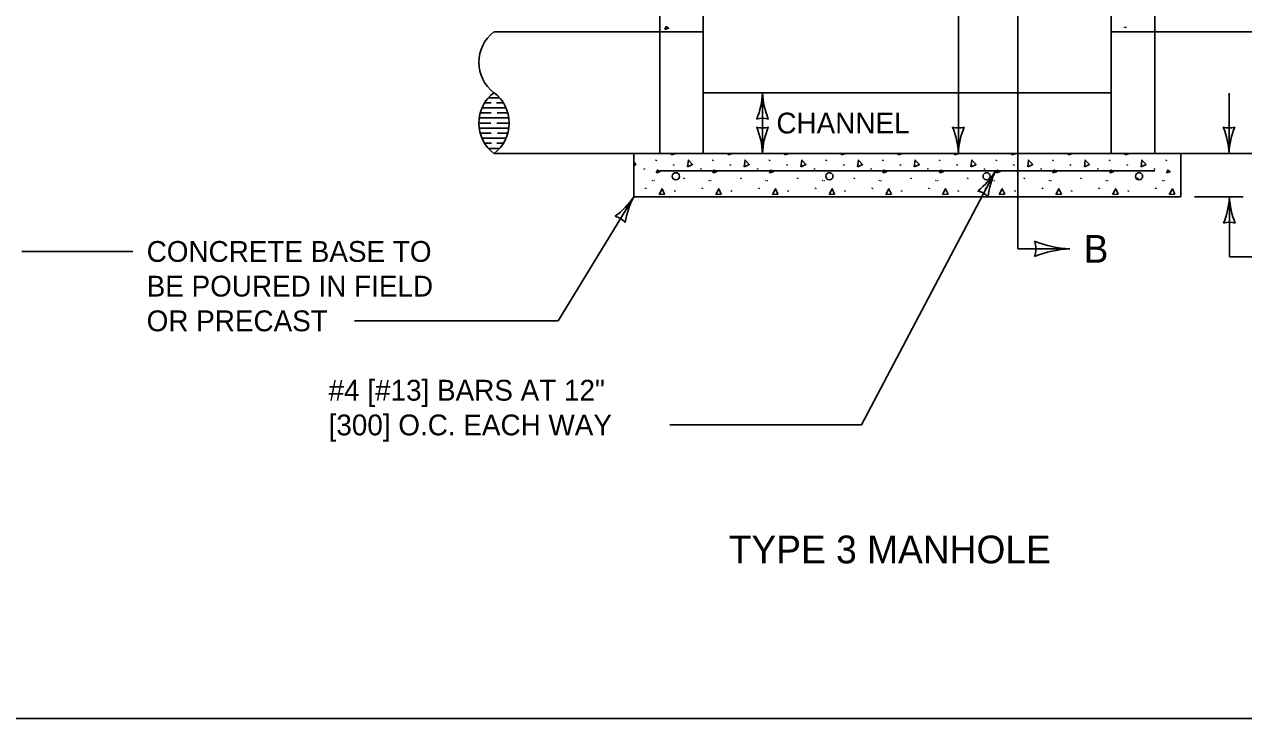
# Model space of a CAD drawing. Extents: x 49991.4 to 50028.3, y 49987.6 to 50011.4.
# Drawn here: x 50005.208 to 50008.719, y 49987.799 to 49989.8 of the extents above; entities that cross this region are included whole.
import ezdxf

# ---------------------------------------------------------------- set-up
doc = ezdxf.new("R2010")
doc.units = 0
for name, color, linetype in [('Level 1', 7, 'Continuous'), ('Level 2', 7, 'Continuous'), ('Level 3', 7, 'Continuous'), ('Level 4', 7, 'Continuous'), ('Level 6', 7, 'Continuous')]:
    doc.layers.add(name, color=color, linetype=linetype)

msp = doc.modelspace()

# ---------------------------------------------------------------- linework, layer by layer
at = {"layer": 'Level 1'}
for p, q in [((50007.0376, 49991.4777), (50007.0376, 49989.7777)), ((50008.4626, 49991.4777), (50008.4626, 49989.7777)), ((50007.1626, 49989.7777), (50006.5599, 49989.7777)), ((50008.3376, 49989.7777), (50008.9435, 49989.7777)), ((50008.3737, 49989.7929), (50008.3751, 49989.7909)), ((50008.3788, 49989.7921), (50008.3801, 49989.7901)), ((50007.1626, 49989.6027), (50008.3376, 49989.6027)), ((50006.533, 49989.5736), (50006.5513, 49989.5736)), ((50006.544, 49989.5882), (50006.5758, 49989.5882)), ((50006.567, 49989.5736), (50006.5868, 49989.5736)), ((50006.5201, 49989.5444), (50006.552, 49989.5444)), ((50006.5253, 49989.559), (50006.5945, 49989.559)), ((50006.5693, 49989.5444), (50006.5997, 49989.5444)), ((50006.5161, 49989.5152), (50006.5505, 49989.5152)), ((50006.5171, 49989.5298), (50006.6027, 49989.5298)), ((50006.5171, 49989.5007), (50006.6027, 49989.5007)), ((50006.5677, 49989.5152), (50006.6036, 49989.5152)), ((50006.5201, 49989.4861), (50006.5513, 49989.4861)), ((50006.5253, 49989.4715), (50006.5945, 49989.4715)), ((50006.57, 49989.4861), (50006.5997, 49989.4861)), ((50006.533, 49989.4569), (50006.5527, 49989.4569)), ((50006.544, 49989.4423), (50006.5758, 49989.4423)), ((50007.1626, 49989.4277), (50006.5599, 49989.4277)), ((50006.5684, 49989.4569), (50006.5868, 49989.4569)), ((50006.9626, 49989.4277), (50006.9626, 49989.3027)), ((50008.3376, 49989.4277), (50008.9435, 49989.4277)), ((50008.5376, 49989.4277), (50008.5376, 49989.3027)), ((50007.0261, 49989.4064), (50007.0274, 49989.4094)), ((50007.0767, 49989.3928), (50007.078, 49989.3958)), ((50007.1893, 49989.4064), (50007.1907, 49989.4094)), ((50007.2399, 49989.3928), (50007.2413, 49989.3958)), ((50007.3526, 49989.4064), (50007.3539, 49989.4094)), ((50007.4032, 49989.3928), (50007.4045, 49989.3958)), ((50007.5159, 49989.4064), (50007.5172, 49989.4094)), ((50007.5665, 49989.3928), (50007.5678, 49989.3958)), ((50007.6791, 49989.4064), (50007.6805, 49989.4094)), ((50007.7297, 49989.3928), (50007.7311, 49989.3958)), ((50007.8424, 49989.4064), (50007.8437, 49989.4094)), ((50007.893, 49989.3928), (50007.8943, 49989.3958)), ((50008.0057, 49989.4064), (50008.007, 49989.4094)), ((50008.0563, 49989.3928), (50008.0576, 49989.3958)), ((50008.1689, 49989.4064), (50008.1703, 49989.4094)), ((50008.2195, 49989.3928), (50008.2209, 49989.3958)), ((50008.3322, 49989.4064), (50008.3335, 49989.4094)), ((50008.3828, 49989.3928), (50008.3841, 49989.3958)), ((50008.4955, 49989.4064), (50008.4968, 49989.4094)), ((50006.9926, 49989.3844), (50006.9929, 49989.3814)), ((50007.0376, 49989.3777), (50008.4626, 49989.3777)), ((50007.107, 49989.3541), (50007.1083, 49989.3571)), ((50007.1559, 49989.3844), (50007.1562, 49989.3814)), ((50007.2703, 49989.3541), (50007.2716, 49989.3571)), ((50007.3191, 49989.3844), (50007.3195, 49989.3814)), ((50007.4335, 49989.3541), (50007.4349, 49989.3571)), ((50007.4824, 49989.3844), (50007.4827, 49989.3814)), ((50007.5968, 49989.3541), (50007.5981, 49989.3571)), ((50007.6457, 49989.3844), (50007.646, 49989.3814)), ((50007.7601, 49989.3541), (50007.7614, 49989.3571)), ((50007.8089, 49989.3844), (50007.8093, 49989.3814)), ((50007.9233, 49989.3541), (50007.9247, 49989.3571)), ((50007.9722, 49989.3844), (50007.9725, 49989.3814)), ((50008.0866, 49989.3541), (50008.0879, 49989.3571)), ((50008.1355, 49989.3844), (50008.1358, 49989.3814)), ((50008.2499, 49989.3541), (50008.2512, 49989.3571)), ((50008.2987, 49989.3844), (50008.2991, 49989.3814)), ((50008.4131, 49989.3541), (50008.4145, 49989.3571)), ((50008.462, 49989.3844), (50008.4623, 49989.3814)), ((50006.9957, 49989.3256), (50006.997, 49989.3285)), ((50007.0153, 49989.3503), (50007.0167, 49989.3483)), ((50007.0204, 49989.3495), (50007.0217, 49989.3475)), ((50007.08, 49989.3179), (50007.0813, 49989.3209)), ((50007.1589, 49989.3256), (50007.1603, 49989.3285)), ((50007.1786, 49989.3503), (50007.1799, 49989.3483)), ((50007.1837, 49989.3495), (50007.185, 49989.3475)), ((50007.2433, 49989.3179), (50007.2446, 49989.3209)), ((50007.3222, 49989.3256), (50007.3235, 49989.3285)), ((50007.3419, 49989.3503), (50007.3432, 49989.3483)), ((50007.3469, 49989.3495), (50007.3483, 49989.3475)), ((50007.4065, 49989.3179), (50007.4079, 49989.3209)), ((50007.4855, 49989.3256), (50007.4868, 49989.3285)), ((50007.5051, 49989.3503), (50007.5065, 49989.3483)), ((50007.5102, 49989.3495), (50007.5115, 49989.3475)), ((50007.5698, 49989.3179), (50007.5711, 49989.3209)), ((50007.6487, 49989.3256), (50007.6501, 49989.3285)), ((50007.6684, 49989.3503), (50007.6697, 49989.3483)), ((50007.6735, 49989.3495), (50007.6748, 49989.3475)), ((50007.7331, 49989.3179), (50007.7344, 49989.3209)), ((50007.812, 49989.3256), (50007.8133, 49989.3285)), ((50007.8317, 49989.3503), (50007.833, 49989.3483)), ((50007.8367, 49989.3495), (50007.8381, 49989.3475)), ((50007.8963, 49989.3179), (50007.8977, 49989.3209)), ((50007.9753, 49989.3256), (50007.9766, 49989.3285)), ((50007.9949, 49989.3503), (50007.9963, 49989.3483)), ((50008, 49989.3495), (50008.0013, 49989.3475)), ((50008.0596, 49989.3179), (50008.0609, 49989.3209)), ((50008.1385, 49989.3256), (50008.1399, 49989.3285)), ((50008.1582, 49989.3503), (50008.1595, 49989.3483)), ((50008.1633, 49989.3495), (50008.1646, 49989.3475)), ((50008.2229, 49989.3179), (50008.2242, 49989.3209)), ((50008.3018, 49989.3256), (50008.3031, 49989.3285)), ((50008.3215, 49989.3503), (50008.3228, 49989.3483)), ((50008.3265, 49989.3495), (50008.3279, 49989.3475)), ((50008.3861, 49989.3179), (50008.3875, 49989.3209)), ((50008.4651, 49989.3256), (50008.4664, 49989.3285)), ((50008.4847, 49989.3503), (50008.4861, 49989.3483)), ((50008.4898, 49989.3495), (50008.4911, 49989.3475)), ((50006.9626, 49989.3027), (50008.5376, 49989.3027))]:
    msp.add_line(p, q, dxfattribs=at)
for points in [[(49999.3835, 49998.9992), (50016.7501, 49998.9992), (50016.7501, 49987.7988), (49999.3835, 49987.7988)], [(50007.1626, 49991.4777), (50008.3376, 49991.4777), (50008.3376, 49989.4277), (50007.1626, 49989.4277)]]:
    msp.add_lwpolyline(points, close=True, dxfattribs=at)
for points in [[(50007.0521, 49989.7849), (50007.0561, 49989.7933), (50007.0627, 49989.7883), (50007.0521, 49989.7849)], [(50007.0701, 49989.4236), (50007.072, 49989.4277)], [(50007.0798, 49989.4277), (50007.0807, 49989.4269), (50007.0701, 49989.4236)], [(50007.2333, 49989.4236), (50007.2353, 49989.4277)], [(50007.243, 49989.4277), (50007.244, 49989.4269), (50007.2333, 49989.4236)], [(50007.3966, 49989.4236), (50007.3986, 49989.4277)], [(50007.4063, 49989.4277), (50007.4073, 49989.4269), (50007.3966, 49989.4236)], [(50007.5599, 49989.4236), (50007.5618, 49989.4277)], [(50007.5696, 49989.4277), (50007.5705, 49989.4269), (50007.5599, 49989.4236)], [(50007.7231, 49989.4236), (50007.7251, 49989.4277)], [(50007.7328, 49989.4277), (50007.7338, 49989.4269), (50007.7231, 49989.4236)], [(50007.8864, 49989.4236), (50007.8884, 49989.4277)], [(50007.8961, 49989.4277), (50007.8971, 49989.4269), (50007.8864, 49989.4236)], [(50008.0497, 49989.4236), (50008.0516, 49989.4277)], [(50008.0593, 49989.4277), (50008.0603, 49989.4269), (50008.0497, 49989.4236)], [(50008.2129, 49989.4236), (50008.2149, 49989.4277)], [(50008.2226, 49989.4277), (50008.2236, 49989.4269), (50008.2129, 49989.4236)], [(50008.3762, 49989.4236), (50008.3781, 49989.4277)], [(50008.3859, 49989.4277), (50008.3869, 49989.4269), (50008.3762, 49989.4236)], [(50006.9626, 49989.4021), (50006.9685, 49989.3961), (50006.9626, 49989.3933)], [(50007.1172, 49989.3893), (50007.1198, 49989.4084), (50007.1317, 49989.3961), (50007.1175, 49989.3895)], [(50007.2805, 49989.3893), (50007.2831, 49989.4084), (50007.295, 49989.3961), (50007.2808, 49989.3895)], [(50007.4437, 49989.3893), (50007.4464, 49989.4084), (50007.4583, 49989.3961), (50007.4441, 49989.3895)], [(50007.607, 49989.3893), (50007.6096, 49989.4084), (50007.6215, 49989.3961), (50007.6073, 49989.3895)], [(50007.7703, 49989.3893), (50007.7729, 49989.4084), (50007.7848, 49989.3961), (50007.7706, 49989.3895)], [(50007.9335, 49989.3893), (50007.9361, 49989.4084), (50007.9481, 49989.3961), (50007.9338, 49989.3895)], [(50008.0968, 49989.3893), (50008.0994, 49989.4084), (50008.1113, 49989.3961), (50008.0971, 49989.3895)], [(50008.2601, 49989.3893), (50008.2627, 49989.4084), (50008.2746, 49989.3961), (50008.2604, 49989.3895)], [(50008.4233, 49989.3893), (50008.4259, 49989.4084), (50008.4379, 49989.3961), (50008.4236, 49989.3895)], [(50007.0267, 49989.3715), (50007.0307, 49989.3798), (50007.0374, 49989.3748), (50007.0267, 49989.3715)], [(50007.19, 49989.3715), (50007.194, 49989.3798), (50007.2007, 49989.3748), (50007.19, 49989.3715)], [(50007.3533, 49989.3715), (50007.3573, 49989.3798), (50007.3639, 49989.3748), (50007.3533, 49989.3715)], [(50007.6798, 49989.3715), (50007.6838, 49989.3798), (50007.6905, 49989.3748), (50007.6798, 49989.3715)], [(50007.8431, 49989.3715), (50007.8471, 49989.3798), (50007.8537, 49989.3748), (50007.8431, 49989.3715)], [(50008.0063, 49989.3715), (50008.0103, 49989.3798), (50008.017, 49989.3748), (50008.0063, 49989.3715)], [(50008.1696, 49989.3715), (50008.1736, 49989.3798), (50008.1803, 49989.3748), (50008.1696, 49989.3715)], [(50008.3329, 49989.3715), (50008.3369, 49989.3798), (50008.3435, 49989.3748), (50008.3329, 49989.3715)], [(50008.4961, 49989.3715), (50008.5001, 49989.3798), (50008.5068, 49989.3748), (50008.4961, 49989.3715)], [(50007.0351, 49989.3089), (50007.0441, 49989.3259), (50007.0511, 49989.3103), (50007.0354, 49989.3089)], [(50007.1983, 49989.3089), (50007.2073, 49989.3259), (50007.2143, 49989.3103), (50007.1987, 49989.3089)], [(50007.3616, 49989.3089), (50007.3706, 49989.3259), (50007.3776, 49989.3103), (50007.3619, 49989.3089)], [(50007.5249, 49989.3089), (50007.5339, 49989.3259), (50007.5408, 49989.3103), (50007.5252, 49989.3089)], [(50007.6881, 49989.3089), (50007.6971, 49989.3259), (50007.7041, 49989.3103), (50007.6885, 49989.3089)], [(50007.8514, 49989.3089), (50007.8604, 49989.3259), (50007.8674, 49989.3103), (50007.8517, 49989.3089)], [(50008.0147, 49989.3089), (50008.0237, 49989.3259), (50008.0306, 49989.3103), (50008.015, 49989.3089)], [(50008.1779, 49989.3089), (50008.1869, 49989.3259), (50008.1939, 49989.3103), (50008.1783, 49989.3089)], [(50008.3412, 49989.3089), (50008.3502, 49989.3259), (50008.3572, 49989.3103), (50008.3415, 49989.3089)], [(50008.5045, 49989.3089), (50008.5134, 49989.3259), (50008.5204, 49989.3103), (50008.5048, 49989.3089)]]:
    msp.add_lwpolyline(points, dxfattribs=at)
for centre in [(50007.0836, 49989.3617), (50007.5256, 49989.3617), (50007.9785, 49989.3617), (50008.4174, 49989.3617)]:
    msp.add_circle(centre, 0.0104, dxfattribs=at)
for centre, start, end in [((50006.6255, 49989.6902), 126.8699, 233.1301), ((50006.6255, 49989.5152), 126.8699, 233.1301), ((50006.4943, 49989.5152), 306.8699, 53.1301)]:
    msp.add_arc(centre, 0.1094, start, end, dxfattribs=at)
at = {"layer": 'Level 3'}
for p, q in [((50007.8972, 49990.9607), (50007.8972, 49989.4277)), ((50007.3331, 49989.6027), (50007.3331, 49989.4277)), ((50008.6766, 49989.6011), (50008.6766, 49989.4277)), ((50008.0045, 49989.3777), (50007.6183, 49988.6452)), ((50006.7442, 49988.9452), (50006.9626, 49989.3027)), ((50008.5776, 49989.3027), (50008.7176, 49989.3027)), ((50008.6776, 49989.3027), (50008.6776, 49989.1293)), ((50005.5197, 49989.1452), (50005.2001, 49989.1452)), ((50008.7452, 49989.1293), (50008.6776, 49989.1293)), ((50006.1582, 49988.9452), (50006.7442, 49988.9452)), ((50007.6183, 49988.6452), (50007.0662, 49988.6452))]:
    msp.add_line(p, q, dxfattribs=at)
for centre, radius, start, end in [((50007.111, 49989.6119), 0.2223, 337.456, 357.6395), ((50007.5658, 49989.6142), 0.233, 182.8273, 202.0772), ((50007.3331, 49989.4745), 0.0548, 72.1388, 107.8612), ((50007.3331, 49989.5559), 0.0548, 252.1388, 287.8612), ((50007.1004, 49989.4162), 0.233, 2.8273, 22.0772), ((50007.5552, 49989.4186), 0.2223, 157.456, 177.6395), ((50007.8972, 49989.5559), 0.0548, 252.1388, 287.8612), ((50007.6645, 49989.4162), 0.233, 2.8273, 22.0772), ((50008.1194, 49989.4186), 0.2223, 157.456, 177.6395), ((50008.6766, 49989.5559), 0.0548, 252.1388, 287.8612), ((50008.4439, 49989.4162), 0.233, 2.8273, 22.0772), ((50008.8987, 49989.4186), 0.2223, 157.456, 177.6395), ((50007.8143, 49989.4928), 0.2223, 308.6595, 328.843), ((50008.214, 49989.2757), 0.233, 154.0308, 173.2806), ((50006.7778, 49989.4263), 0.2223, 306.0359, 326.2194), ((50007.1672, 49989.1912), 0.233, 151.4072, 170.657), ((50007.9428, 49989.2654), 0.0548, 43.3423, 79.0646), ((50008.4555, 49989.3119), 0.2223, 337.456, 357.6395), ((50008.9103, 49989.3142), 0.233, 182.8273, 202.0772), ((50006.8958, 49989.1933), 0.0548, 40.7187, 76.441), ((50008.6776, 49989.1745), 0.0548, 72.1388, 107.8612), ((50008.2302, 49989.4489), 0.2964, 247.456, 267.6395), ((50008.0471, 49989.1527), 0.073, 342.1388, 17.8612), ((50008.2333, 49988.8424), 0.3107, 92.8273, 112.0772)]:
    msp.add_arc(centre, radius, start, end, dxfattribs=at)
at = {"layer": 'Level 4'}
for p, q in [((50007.0376, 49989.4277), (50007.0376, 49989.7777)), ((50008.4626, 49989.4277), (50008.4626, 49989.7777))]:
    msp.add_line(p, q, dxfattribs=at)
at = {"layer": 'Level 6'}
for p, q in [((50008.068, 49989.9833), (50008.068, 49989.1527)), ((50008.068, 49989.1527), (50008.218, 49989.1527))]:
    msp.add_line(p, q, dxfattribs=at)

# ---------------------------------------------------------------- texts
at = {"layer": 'Level 2'}
for s, height, p in [('CHANNEL', 0.06, (50007.3731, 49989.4852)), ('B', 0.0799, (50008.258, 49989.1127)), ('CONCRETE BASE TO', 0.06, (50005.5597, 49989.1152)), ('BE POURED IN FIELD', 0.06, (50005.5597, 49989.0152)), ('OR PRECAST', 0.06, (50005.5597, 49988.9152)), ('#4 [#13] BARS AT 12"', 0.06, (50006.0836, 49988.7152)), ('[300] O.C. EACH WAY', 0.06, (50006.0836, 49988.6152)), ('TYPE 3 MANHOLE', 0.08, (50007.2359, 49988.2464))]:
    msp.add_text(s, height=height, dxfattribs=at).set_placement(p)

doc.saveas('drawing.dxf')
